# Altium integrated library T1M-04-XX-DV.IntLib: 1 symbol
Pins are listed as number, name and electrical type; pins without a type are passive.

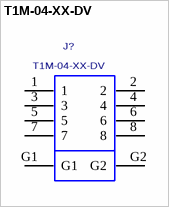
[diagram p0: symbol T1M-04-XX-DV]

## T1M-04-XX-DV
designator J?
1 MM DOUBLE ROW DISCRETE WIRE HEADER, 8 PINS.; MANUFACTURER: SAMTEC
footprint T1M-04-XX-DV
pins: 1, 2, 3, 4, 5, 6, 7, 8, G1, G2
